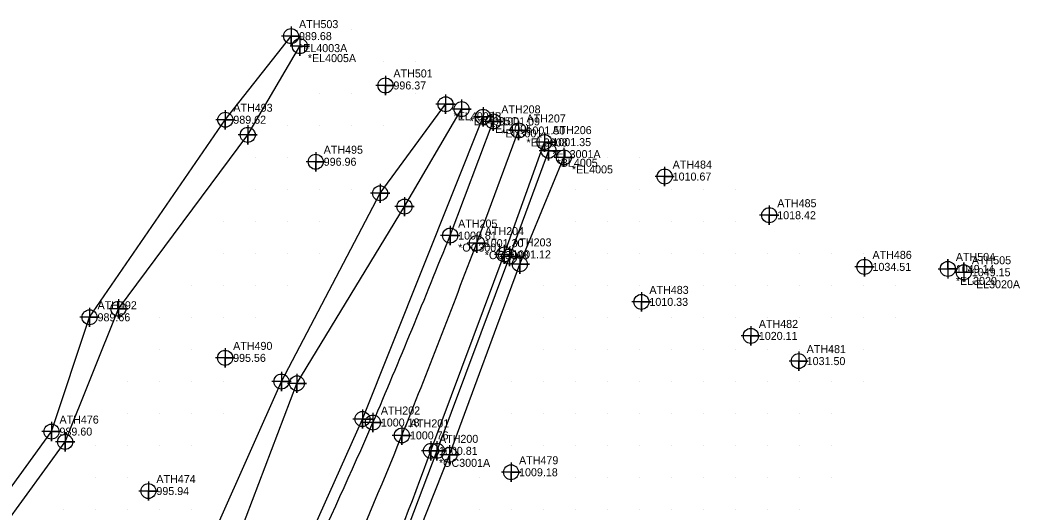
# Model space of a CAD drawing. Extents: x 1116680 to 1117499, y 661040 to 661703.
# Drawn here: x 1117186.4 to 1117498.8, y 661549.3 to 661703 of the extents above; entities that cross this region are included whole.
import ezdxf

# ---------------------------------------------------------------- set-up
doc = ezdxf.new("R2010")
doc.units = 0
for name, color, linetype in [('Exist DTM Breakline', 7, 'Continuous'), ('Exist DTM Breakline Cogo Comment', 7, 'Continuous'), ('Exist DTM Breakline Cogo Point CELL', 7, 'Continuous'), ('Exist DTM Crownline', 7, 'Continuous'), ('Exist DTM Crownline Cogo Comment', 7, 'Continuous'), ('Exist DTM Crownline Cogo Elevation', 7, 'Continuous'), ('Exist DTM Crownline Cogo Number', 7, 'Continuous'), ('Exist DTM Crownline Cogo Point CELL', 7, 'Continuous'), ('Exist DTM Drainline Cogo Comment', 7, 'Continuous'), ('Exist DTM Drainline Cogo Elevation', 7, 'Continuous'), ('Exist DTM Drainline Cogo Number', 7, 'Continuous'), ('Exist DTM Drainline Cogo Point CELL', 7, 'Continuous'), ('Exist DTM QL2 LIDAR Elevation Point', 7, 'Continuous'), ('Exist DTM Regular Point CELL', 7, 'Continuous'), ('Exist DTM Regular Point Cogo Elevation', 7, 'Continuous'), ('Exist DTM Regular Point Cogo Number', 7, 'Continuous'), ('Exist Hydro Stream or Body of Water', 7, 'Continuous'), ('Exist Railroads Standard Gauge Cogo Comment', 7, 'Continuous'), ('Exist Railroads Standard Gauge Cogo Elevation', 7, 'Continuous'), ('Exist Railroads Standard Gauge Cogo Number', 7, 'Continuous'), ('Exist Railroads Standard Gauge Cogo Point CELL', 7, 'Continuous'), ('Exist Roads EOP', 7, 'Continuous'), ('Exist Roads EOP Cogo Comment', 7, 'Continuous'), ('Exist Roads EOP Cogo Elevation', 7, 'Continuous'), ('Exist Roads EOP Cogo Number', 7, 'Continuous'), ('Exist Roads EOP Cogo Point CELL', 7, 'Continuous')]:
    doc.layers.add(name, color=color, linetype=linetype)

msp = doc.modelspace()

# ---------------------------------------------------------------- linework, layer by layer
at = {"layer": 'Exist DTM Breakline'}
for points in [[(1117128.128, 661464.169), (1117144.878, 661495.181), (1117168.704, 661527.446), (1117200.502, 661571.22), (1117217.144, 661612.812), (1117257.559, 661667.144), (1117273.855, 661694.87)], [(1117207.028, 661459.166), (1117233.018, 661490.613), (1117248.28, 661545.62), (1117268.093, 661590.069), (1117298.919, 661648.887), (1117319.378, 661676.709)], [(1117210.127, 661456.793), (1117237.863, 661487.331), (1117272.992, 661532.718), (1117293.41, 661578.363), (1117331.106, 661672.763)], [(1117241.093, 661491.753), (1117255.131, 661542.605), (1117272.944, 661589.509), (1117306.544, 661644.722), (1117324.4, 661675.172)], [(1117161.696, 661291.017), (1117168.482, 661312.597), (1117176.266, 661342.559), (1117182.941, 661374.652), (1117194.026, 661386.336), (1117220.943, 661405.14), (1117272.33, 661460.939), (1117291.277, 661496.211), (1117300.472, 661516.498), (1117320.583, 661567.148), (1117342.592, 661626.703), (1117356.346, 661660.105)], [(1117351.58, 661662.175), (1117339.299, 661629.132), (1117316.671, 661568.431), (1117298.876, 661521.377), (1117271.145, 661466.692), (1117239.817, 661428.377), (1117194.27, 661391.492)]]:
    msp.add_lwpolyline(points, dxfattribs=at)
at = {"layer": 'Exist DTM Breakline Cogo Point CELL'}
for points in [[(1117273.855, 661697.87), (1117273.855, 661691.87), (1117273.855, 661694.87), (1117276.855, 661694.87), (1117270.855, 661694.87)], [(1117319.378, 661679.709), (1117319.378, 661673.709), (1117319.378, 661676.709), (1117322.378, 661676.709), (1117316.378, 661676.709)], [(1117324.4, 661678.172), (1117324.4, 661672.172), (1117324.4, 661675.172), (1117327.4, 661675.172), (1117321.4, 661675.172)], [(1117331.106, 661675.763), (1117331.106, 661669.763), (1117331.106, 661672.763), (1117334.106, 661672.763), (1117328.106, 661672.763)], [(1117257.559, 661670.144), (1117257.559, 661664.144), (1117257.559, 661667.144), (1117260.559, 661667.144), (1117254.559, 661667.144)], [(1117351.58, 661665.175), (1117351.58, 661659.175), (1117351.58, 661662.175), (1117354.58, 661662.175), (1117348.58, 661662.175)], [(1117356.346, 661663.105), (1117356.346, 661657.105), (1117356.346, 661660.105), (1117359.346, 661660.105), (1117353.346, 661660.105)], [(1117298.919, 661651.887), (1117298.919, 661645.887), (1117298.919, 661648.887), (1117301.919, 661648.887), (1117295.919, 661648.887)], [(1117306.544, 661647.722), (1117306.544, 661641.722), (1117306.544, 661644.722), (1117309.544, 661644.722), (1117303.544, 661644.722)], [(1117339.299, 661632.132), (1117339.299, 661626.132), (1117339.299, 661629.132), (1117342.299, 661629.132), (1117336.299, 661629.132)], [(1117342.592, 661629.703), (1117342.592, 661623.703), (1117342.592, 661626.703), (1117345.592, 661626.703), (1117339.592, 661626.703)], [(1117217.144, 661615.812), (1117217.144, 661609.812), (1117217.144, 661612.812), (1117220.144, 661612.812), (1117214.144, 661612.812)], [(1117268.093, 661593.069), (1117268.093, 661587.069), (1117268.093, 661590.069), (1117271.093, 661590.069), (1117265.093, 661590.069)], [(1117272.944, 661592.509), (1117272.944, 661586.509), (1117272.944, 661589.509), (1117275.944, 661589.509), (1117269.944, 661589.509)], [(1117293.41, 661581.363), (1117293.41, 661575.363), (1117293.41, 661578.363), (1117296.41, 661578.363), (1117290.41, 661578.363)], [(1117200.502, 661574.22), (1117200.502, 661568.22), (1117200.502, 661571.22), (1117203.502, 661571.22), (1117197.502, 661571.22)], [(1117316.671, 661571.431), (1117316.671, 661565.431), (1117316.671, 661568.431), (1117319.671, 661568.431), (1117313.671, 661568.431)], [(1117320.583, 661570.148), (1117320.583, 661564.148), (1117320.583, 661567.148), (1117323.583, 661567.148), (1117317.583, 661567.148)]]:
    msp.add_lwpolyline(points, dxfattribs=at)
for centre in [(1117273.855, 661694.87), (1117319.378, 661676.709), (1117324.4, 661675.172), (1117331.106, 661672.763), (1117257.559, 661667.144), (1117351.58, 661662.175), (1117356.346, 661660.105), (1117298.919, 661648.887), (1117306.544, 661644.722), (1117339.299, 661629.132), (1117342.592, 661626.703), (1117217.144, 661612.812), (1117268.093, 661590.069), (1117272.944, 661589.509), (1117293.41, 661578.363), (1117200.502, 661571.22), (1117316.671, 661568.431), (1117320.583, 661567.148)]:
    msp.add_circle(centre, 2.344, dxfattribs=at)
at = {"layer": 'Exist DTM Crownline'}
msp.add_line((1117329.129, 661633.315), (1117342.162, 661668.519), dxfattribs=at)
msp.add_spline([(1117128.608, 661382.881), (1117161.083, 661393.544), (1117193.928, 661410.345), (1117229.679, 661438.384), (1117257.918, 661472.931), (1117285.234, 661525.056), (1117305.735, 661573.245), (1117329.129, 661633.315)], degree=3, dxfattribs=at)
at = {"layer": 'Exist DTM Crownline Cogo Point CELL'}
for points in [[(1117342.162, 661671.519), (1117342.162, 661665.519), (1117342.162, 661668.519), (1117345.162, 661668.519), (1117339.162, 661668.519)], [(1117329.129, 661636.315), (1117329.129, 661630.315), (1117329.129, 661633.315), (1117332.129, 661633.315), (1117326.129, 661633.315)], [(1117305.735, 661576.245), (1117305.735, 661570.245), (1117305.735, 661573.245), (1117308.735, 661573.245), (1117302.735, 661573.245)]]:
    msp.add_lwpolyline(points, dxfattribs=at)
for centre in [(1117342.162, 661668.519), (1117329.129, 661633.315), (1117305.735, 661573.245)]:
    msp.add_circle(centre, 2.344, dxfattribs=at)
at = {"layer": 'Exist DTM Drainline Cogo Point CELL'}
for points in [[(1117271.101, 661700.995), (1117271.101, 661694.995), (1117271.101, 661697.995), (1117274.101, 661697.995), (1117268.101, 661697.995)], [(1117250.567, 661674.867), (1117250.567, 661668.867), (1117250.567, 661671.867), (1117253.567, 661671.867), (1117247.567, 661671.867)], [(1117208.146, 661613.151), (1117208.146, 661607.151), (1117208.146, 661610.151), (1117211.146, 661610.151), (1117205.146, 661610.151)], [(1117196.253, 661577.433), (1117196.253, 661571.433), (1117196.253, 661574.433), (1117199.253, 661574.433), (1117193.253, 661574.433)]]:
    msp.add_lwpolyline(points, dxfattribs=at)
for centre in [(1117271.101, 661697.995), (1117250.567, 661671.867), (1117208.146, 661610.151), (1117196.253, 661574.433)]:
    msp.add_circle(centre, 2.344, dxfattribs=at)
at = {"layer": 'Exist DTM QL2 LIDAR Elevation Point'}
for p, q in [((1117290, 661700), (1117290, 661700)), ((1117280, 661690), (1117280, 661690)), ((1117290, 661690), (1117290, 661690)), ((1117300, 661690), (1117300, 661690)), ((1117310, 661690), (1117310, 661690)), ((1117280, 661680), (1117280, 661680)), ((1117290, 661680), (1117290, 661680)), ((1117310, 661680), (1117310, 661680)), ((1117270, 661670), (1117270, 661670)), ((1117280, 661670), (1117280, 661670)), ((1117290, 661670), (1117290, 661670)), ((1117300, 661670), (1117300, 661670)), ((1117260, 661660), (1117260, 661660)), ((1117270, 661660), (1117270, 661660)), ((1117290, 661660), (1117290, 661660)), ((1117370, 661660), (1117370, 661660)), ((1117380, 661660), (1117380, 661660)), ((1117260, 661650), (1117260, 661650)), ((1117270, 661650), (1117270, 661650)), ((1117280, 661650), (1117280, 661650)), ((1117290, 661650), (1117290, 661650)), ((1117360, 661650), (1117360, 661650)), ((1117370, 661650), (1117370, 661650)), ((1117380, 661650), (1117380, 661650)), ((1117390, 661650), (1117390, 661650)), ((1117400, 661650), (1117400, 661650)), ((1117410, 661650), (1117410, 661650)), ((1117250, 661640), (1117250, 661640)), ((1117260, 661640), (1117260, 661640)), ((1117270, 661640), (1117270, 661640)), ((1117280, 661640), (1117280, 661640)), ((1117360, 661640), (1117360, 661640)), ((1117370, 661640), (1117370, 661640)), ((1117380, 661640), (1117380, 661640)), ((1117390, 661640), (1117390, 661640)), ((1117400, 661640), (1117400, 661640)), ((1117410, 661640), (1117410, 661640)), ((1117420, 661640), (1117420, 661640)), ((1117430, 661640), (1117430, 661640)), ((1117250, 661630), (1117250, 661630)), ((1117260, 661630), (1117260, 661630)), ((1117270, 661630), (1117270, 661630)), ((1117280, 661630), (1117280, 661630)), ((1117360, 661630), (1117360, 661630)), ((1117370, 661630), (1117370, 661630)), ((1117380, 661630), (1117380, 661630)), ((1117390, 661630), (1117390, 661630)), ((1117400, 661630), (1117400, 661630)), ((1117410, 661630), (1117410, 661630)), ((1117420, 661630), (1117420, 661630)), ((1117430, 661630), (1117430, 661630)), ((1117440, 661630), (1117440, 661630)), ((1117450, 661630), (1117450, 661630)), ((1117460, 661630), (1117460, 661630)), ((1117240, 661620), (1117240, 661620)), ((1117250, 661620), (1117250, 661620)), ((1117260, 661620), (1117260, 661620)), ((1117270, 661620), (1117270, 661620)), ((1117350, 661620), (1117350, 661620)), ((1117360, 661620), (1117360, 661620)), ((1117370, 661620), (1117370, 661620)), ((1117380, 661620), (1117380, 661620)), ((1117390, 661620), (1117390, 661620)), ((1117400, 661620), (1117400, 661620)), ((1117410, 661620), (1117410, 661620)), ((1117420, 661620), (1117420, 661620)), ((1117430, 661620), (1117430, 661620)), ((1117440, 661620), (1117440, 661620)), ((1117450, 661620), (1117450, 661620)), ((1117460, 661620), (1117460, 661620)), ((1117230, 661610), (1117230, 661610)), ((1117240, 661610), (1117240, 661610)), ((1117250, 661610), (1117250, 661610)), ((1117260, 661610), (1117260, 661610)), ((1117350, 661610), (1117350, 661610)), ((1117360, 661610), (1117360, 661610)), ((1117370, 661610), (1117370, 661610)), ((1117380, 661610), (1117380, 661610)), ((1117390, 661610), (1117390, 661610)), ((1117400, 661610), (1117400, 661610)), ((1117410, 661610), (1117410, 661610)), ((1117420, 661610), (1117420, 661610)), ((1117430, 661610), (1117430, 661610)), ((1117440, 661610), (1117440, 661610)), ((1117450, 661610), (1117450, 661610)), ((1117460, 661610), (1117460, 661610)), ((1117230, 661600), (1117230, 661600)), ((1117240, 661600), (1117240, 661600)), ((1117250, 661600), (1117250, 661600)), ((1117260, 661600), (1117260, 661600)), ((1117350, 661600), (1117350, 661600)), ((1117360, 661600), (1117360, 661600)), ((1117370, 661600), (1117370, 661600)), ((1117380, 661600), (1117380, 661600)), ((1117390, 661600), (1117390, 661600)), ((1117400, 661600), (1117400, 661600)), ((1117410, 661600), (1117410, 661600)), ((1117420, 661600), (1117420, 661600)), ((1117430, 661600), (1117430, 661600)), ((1117440, 661600), (1117440, 661600)), ((1117450, 661600), (1117450, 661600)), ((1117220, 661590), (1117220, 661590)), ((1117230, 661590), (1117230, 661590)), ((1117240, 661590), (1117240, 661590)), ((1117250, 661590), (1117250, 661590)), ((1117340, 661590), (1117340, 661590)), ((1117350, 661590), (1117350, 661590)), ((1117360, 661590), (1117360, 661590)), ((1117370, 661590), (1117370, 661590)), ((1117380, 661590), (1117380, 661590)), ((1117390, 661590), (1117390, 661590)), ((1117400, 661590), (1117400, 661590)), ((1117410, 661590), (1117410, 661590)), ((1117420, 661590), (1117420, 661590)), ((1117430, 661590), (1117430, 661590)), ((1117440, 661590), (1117440, 661590)), ((1117450, 661590), (1117450, 661590)), ((1117220, 661580), (1117220, 661580)), ((1117230, 661580), (1117230, 661580)), ((1117240, 661580), (1117240, 661580)), ((1117250, 661580), (1117250, 661580)), ((1117340, 661580), (1117340, 661580)), ((1117350, 661580), (1117350, 661580)), ((1117360, 661580), (1117360, 661580)), ((1117370, 661580), (1117370, 661580)), ((1117380, 661580), (1117380, 661580)), ((1117390, 661580), (1117390, 661580)), ((1117400, 661580), (1117400, 661580)), ((1117410, 661580), (1117410, 661580)), ((1117420, 661580), (1117420, 661580)), ((1117430, 661580), (1117430, 661580)), ((1117440, 661580), (1117440, 661580)), ((1117210, 661570), (1117210, 661570)), ((1117220, 661570), (1117220, 661570)), ((1117230, 661570), (1117230, 661570)), ((1117240, 661570), (1117240, 661570)), ((1117340, 661570), (1117340, 661570)), ((1117350, 661570), (1117350, 661570)), ((1117360, 661570), (1117360, 661570)), ((1117370, 661570), (1117370, 661570)), ((1117380, 661570), (1117380, 661570)), ((1117390, 661570), (1117390, 661570)), ((1117400, 661570), (1117400, 661570)), ((1117410, 661570), (1117410, 661570)), ((1117420, 661570), (1117420, 661570)), ((1117430, 661570), (1117430, 661570)), ((1117440, 661570), (1117440, 661570)), ((1117210, 661560), (1117210, 661560)), ((1117220, 661560), (1117220, 661560)), ((1117230, 661560), (1117230, 661560)), ((1117240, 661560), (1117240, 661560)), ((1117330, 661560), (1117330, 661560)), ((1117340, 661560), (1117340, 661560)), ((1117350, 661560), (1117350, 661560)), ((1117360, 661560), (1117360, 661560)), ((1117370, 661560), (1117370, 661560)), ((1117380, 661560), (1117380, 661560)), ((1117390, 661560), (1117390, 661560)), ((1117400, 661560), (1117400, 661560)), ((1117410, 661560), (1117410, 661560)), ((1117420, 661560), (1117420, 661560)), ((1117430, 661560), (1117430, 661560)), ((1117440, 661560), (1117440, 661560)), ((1117200, 661550), (1117200, 661550)), ((1117210, 661550), (1117210, 661550)), ((1117220, 661550), (1117220, 661550)), ((1117230, 661550), (1117230, 661550)), ((1117240, 661550), (1117240, 661550)), ((1117330, 661550), (1117330, 661550)), ((1117340, 661550), (1117340, 661550)), ((1117350, 661550), (1117350, 661550)), ((1117360, 661550), (1117360, 661550)), ((1117370, 661550), (1117370, 661550)), ((1117380, 661550), (1117380, 661550)), ((1117390, 661550), (1117390, 661550)), ((1117400, 661550), (1117400, 661550)), ((1117410, 661550), (1117410, 661550)), ((1117420, 661550), (1117420, 661550)), ((1117430, 661550), (1117430, 661550))]:
    msp.add_line(p, q, dxfattribs=at)
at = {"layer": 'Exist DTM Regular Point CELL'}
for points in [[(1117300.585, 661685.583), (1117300.585, 661679.583), (1117300.585, 661682.583), (1117303.585, 661682.583), (1117297.585, 661682.583)], [(1117278.803, 661661.742), (1117278.803, 661655.742), (1117278.803, 661658.742), (1117281.803, 661658.742), (1117275.803, 661658.742)], [(1117387.83, 661657.118), (1117387.83, 661651.118), (1117387.83, 661654.118), (1117390.83, 661654.118), (1117384.83, 661654.118)], [(1117420.503, 661645.04), (1117420.503, 661639.04), (1117420.503, 661642.04), (1117423.503, 661642.04), (1117417.503, 661642.04)], [(1117450.262, 661628.898), (1117450.262, 661622.898), (1117450.262, 661625.898), (1117453.262, 661625.898), (1117447.262, 661625.898)], [(1117380.564, 661617.956), (1117380.564, 661611.956), (1117380.564, 661614.956), (1117383.564, 661614.956), (1117377.564, 661614.956)], [(1117414.753, 661607.328), (1117414.753, 661601.328), (1117414.753, 661604.328), (1117417.753, 661604.328), (1117411.753, 661604.328)], [(1117250.505, 661600.464), (1117250.505, 661594.464), (1117250.505, 661597.464), (1117253.505, 661597.464), (1117247.505, 661597.464)], [(1117429.704, 661599.462), (1117429.704, 661593.462), (1117429.704, 661596.462), (1117432.704, 661596.462), (1117426.704, 661596.462)], [(1117339.84, 661564.725), (1117339.84, 661558.725), (1117339.84, 661561.725), (1117342.84, 661561.725), (1117336.84, 661561.725)], [(1117226.533, 661558.865), (1117226.533, 661552.865), (1117226.533, 661555.865), (1117229.533, 661555.865), (1117223.533, 661555.865)]]:
    msp.add_lwpolyline(points, dxfattribs=at)
for centre in [(1117300.585, 661682.583), (1117278.803, 661658.742), (1117387.83, 661654.118), (1117420.503, 661642.04), (1117450.262, 661625.898), (1117380.564, 661614.956), (1117414.753, 661604.328), (1117250.505, 661597.464), (1117429.704, 661596.462), (1117339.84, 661561.725), (1117226.533, 661555.865)]:
    msp.add_circle(centre, 2.344, dxfattribs=at)
at = {"layer": 'Exist Hydro Stream or Body of Water'}
msp.add_lwpolyline([(1117125.362, 661468.034), (1117140.152, 661498.019), (1117164.523, 661530.702), (1117196.253, 661574.433), (1117208.146, 661610.151), (1117250.567, 661671.867), (1117271.101, 661697.995)], dxfattribs=at)
at = {"layer": 'Exist Railroads Standard Gauge Cogo Point CELL'}
for points in [[(1117473.298, 661625.26), (1117479.298, 661625.26), (1117476.298, 661625.26), (1117476.298, 661628.26), (1117476.298, 661622.26)], [(1117478.298, 661624.219), (1117484.298, 661624.219), (1117481.298, 661624.219), (1117481.298, 661627.219), (1117481.298, 661621.219)]]:
    msp.add_lwpolyline(points, dxfattribs=at)
for centre in [(1117476.298, 661625.26), (1117481.298, 661624.219)]:
    msp.add_circle(centre, 2.344, dxfattribs=at)
at = {"layer": 'Exist Roads EOP'}
msp.add_line((1117320.803, 661635.676), (1117334.286, 661671.354), dxfattribs=at)
msp.add_lwpolyline([(1117314.821, 661568.418), (1117337.702, 661629.797), (1117350.255, 661664.879)], dxfattribs=at)
for points in [[(1117102.286, 661387.333), (1117126.621, 661394.057), (1117156.418, 661404.979), (1117187.204, 661421.689), (1117219.891, 661448.41), (1117247.012, 661480.823), (1117275.546, 661531.18), (1117296.661, 661577.27), (1117320.803, 661635.676)], [(1117131.334, 661372.856), (1117166.321, 661382.847), (1117200.815, 661399.841), (1117238.067, 661430.322), (1117267.048, 661465.689), (1117295.472, 661519.132), (1117314.821, 661568.418)]]:
    msp.add_spline(points, degree=3, dxfattribs=at)
at = {"layer": 'Exist Roads EOP Cogo Point CELL'}
for points in [[(1117334.286, 661674.354), (1117334.286, 661668.354), (1117334.286, 661671.354), (1117337.286, 661671.354), (1117331.286, 661671.354)], [(1117350.255, 661667.879), (1117350.255, 661661.879), (1117350.255, 661664.879), (1117353.255, 661664.879), (1117347.255, 661664.879)], [(1117320.803, 661638.676), (1117320.803, 661632.676), (1117320.803, 661635.676), (1117323.803, 661635.676), (1117317.803, 661635.676)], [(1117337.702, 661632.797), (1117337.702, 661626.797), (1117337.702, 661629.797), (1117340.702, 661629.797), (1117334.702, 661629.797)], [(1117296.661, 661580.27), (1117296.661, 661574.27), (1117296.661, 661577.27), (1117299.661, 661577.27), (1117293.661, 661577.27)], [(1117314.821, 661571.418), (1117314.821, 661565.418), (1117314.821, 661568.418), (1117317.821, 661568.418), (1117311.821, 661568.418)]]:
    msp.add_lwpolyline(points, dxfattribs=at)
for centre in [(1117334.286, 661671.354), (1117350.255, 661664.879), (1117320.803, 661635.676), (1117337.702, 661629.797), (1117296.661, 661577.27), (1117314.821, 661568.418)]:
    msp.add_circle(centre, 2.344, dxfattribs=at)

# ---------------------------------------------------------------- texts
at = {"layer": 'Exist DTM Breakline Cogo Comment'}
for s, p in [('*EL4005A', (1117276.355, 661689.87)), ('*EL4005B', (1117321.878, 661671.709)), ('*EL4005C', (1117326.9, 661670.172)), ('*EL4005', (1117333.606, 661667.763)), ('*BL4005', (1117354.08, 661657.175)), ('*EL4005', (1117358.846, 661655.105))]:
    msp.add_text(s, height=2.5, dxfattribs=at).set_placement(p)
at = {"layer": 'Exist DTM Crownline Cogo Comment'}
for s, p in [('*EL3008', (1117344.662, 661663.519)), ('*OC3008', (1117331.629, 661628.315))]:
    msp.add_text(s, height=2.5, dxfattribs=at).set_placement(p)
at = {"layer": 'Exist DTM Crownline Cogo Elevation'}
for s, p in [('1001.50', (1117344.662, 661667.269)), ('1001.30', (1117331.629, 661632.065)), ('1000.76', (1117308.235, 661571.995))]:
    msp.add_text(s, height=2.5, dxfattribs=at).set_placement(p)
at = {"layer": 'Exist DTM Crownline Cogo Number'}
for s, p in [('ATH207', (1117344.662, 661671.019)), ('ATH204', (1117331.629, 661635.815)), ('ATH201', (1117308.235, 661575.745))]:
    msp.add_text(s, height=2.5, dxfattribs=at).set_placement(p)
at = {"layer": 'Exist DTM Drainline Cogo Comment'}
msp.add_text('*EL4003A', height=2.5, dxfattribs=at).set_placement((1117273.601, 661692.995))
at = {"layer": 'Exist DTM Drainline Cogo Elevation'}
for s, p in [('989.68', (1117273.601, 661696.745)), ('989.62', (1117253.067, 661670.617)), ('989.66', (1117210.646, 661608.901)), ('989.60', (1117198.753, 661573.183))]:
    msp.add_text(s, height=2.5, dxfattribs=at).set_placement(p)
at = {"layer": 'Exist DTM Drainline Cogo Number'}
for s, p in [('ATH503', (1117273.601, 661700.495)), ('ATH493', (1117253.067, 661674.367)), ('ATH492', (1117210.646, 661612.651)), ('ATH476', (1117198.753, 661576.933))]:
    msp.add_text(s, height=2.5, dxfattribs=at).set_placement(p)
at = {"layer": 'Exist DTM Regular Point Cogo Elevation'}
for s, p in [('996.37', (1117303.085, 661681.333)), ('996.96', (1117281.303, 661657.492)), ('1010.67', (1117390.33, 661652.868)), ('1018.42', (1117423.003, 661640.79)), ('1034.51', (1117452.762, 661624.648)), ('1010.33', (1117383.064, 661613.706)), ('1020.11', (1117417.253, 661603.078)), ('995.56', (1117253.005, 661596.214)), ('1031.50', (1117432.204, 661595.212)), ('1009.18', (1117342.34, 661560.475)), ('995.94', (1117229.033, 661554.615))]:
    msp.add_text(s, height=2.5, dxfattribs=at).set_placement(p)
at = {"layer": 'Exist DTM Regular Point Cogo Number'}
for s, p in [('ATH501', (1117303.085, 661685.083)), ('ATH495', (1117281.303, 661661.242)), ('ATH484', (1117390.33, 661656.618)), ('ATH485', (1117423.003, 661644.54)), ('ATH486', (1117452.762, 661628.398)), ('ATH483', (1117383.064, 661617.456)), ('ATH482', (1117417.253, 661606.828)), ('ATH490', (1117253.005, 661599.964)), ('ATH481', (1117432.204, 661598.962)), ('ATH479', (1117342.34, 661564.225)), ('ATH474', (1117229.033, 661558.365))]:
    msp.add_text(s, height=2.5, dxfattribs=at).set_placement(p)
at = {"layer": 'Exist Railroads Standard Gauge Cogo Comment'}
for s, p in [('*EL3020', (1117478.798, 661620.26)), ('*EL3020A', (1117483.798, 661619.219))]:
    msp.add_text(s, height=2.5, dxfattribs=at).set_placement(p)
at = {"layer": 'Exist Railroads Standard Gauge Cogo Elevation'}
for s, p in [('1049.14', (1117478.798, 661624.01)), ('1049.15', (1117483.798, 661622.969))]:
    msp.add_text(s, height=2.5, dxfattribs=at).set_placement(p)
at = {"layer": 'Exist Railroads Standard Gauge Cogo Number'}
for s, p in [('ATH504', (1117478.798, 661627.76)), ('ATH505', (1117483.798, 661626.719))]:
    msp.add_text(s, height=2.5, dxfattribs=at).set_placement(p)
at = {"layer": 'Exist Roads EOP Cogo Comment'}
for s, p in [('*EL3001', (1117336.786, 661666.354)), ('*EL3001A', (1117352.755, 661659.879)), ('*OC3001', (1117323.303, 661630.676)), ('*OC3001A', (1117317.321, 661563.418))]:
    msp.add_text(s, height=2.5, dxfattribs=at).set_placement(p)
at = {"layer": 'Exist Roads EOP Cogo Elevation'}
for s, p in [('1001.09', (1117336.786, 661670.104)), ('1001.35', (1117352.755, 661663.629)), ('1000.81', (1117323.303, 661634.426)), ('1001.12', (1117340.202, 661628.547)), ('1000.18', (1117299.161, 661576.02)), ('1000.81', (1117317.321, 661567.168))]:
    msp.add_text(s, height=2.5, dxfattribs=at).set_placement(p)
at = {"layer": 'Exist Roads EOP Cogo Number'}
for s, p in [('ATH208', (1117336.786, 661673.854)), ('ATH206', (1117352.755, 661667.379)), ('ATH205', (1117323.303, 661638.176)), ('ATH203', (1117340.202, 661632.297)), ('ATH202', (1117299.161, 661579.77)), ('ATH200', (1117317.321, 661570.918))]:
    msp.add_text(s, height=2.5, dxfattribs=at).set_placement(p)

doc.saveas('drawing.dxf')
